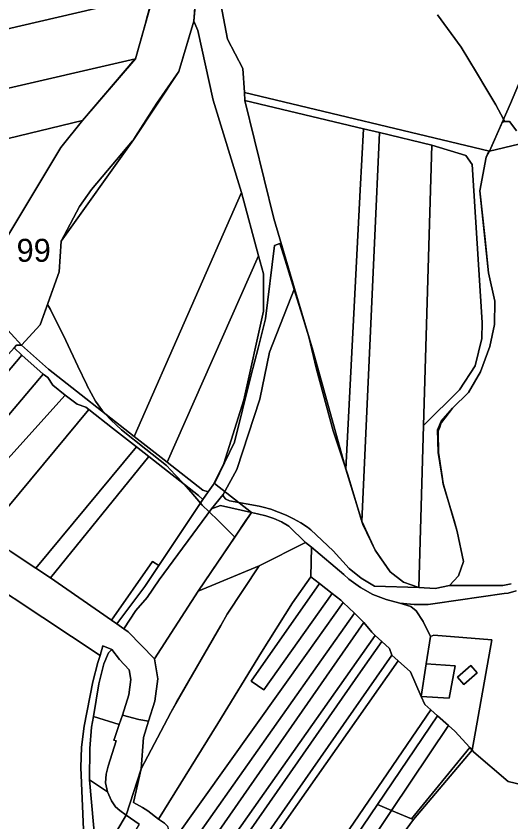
# Model space of a CAD drawing. Extents: x -521939 to -516426, y -1197857 to -1189551.
# Drawn here: x -519055 to -518732, y -1194197 to -1193670 of the extents above; entities that cross this region are included whole.
import ezdxf

# ---------------------------------------------------------------- set-up
doc = ezdxf.new("R2010")
doc.units = 0
for name, color, linetype in [('95560013', 7, 'Continuous'), ('95600013', 7, 'Continuous'), ('95610013', 7, 'Continuous'), ('95620013', 7, 'Continuous'), ('95630013', 7, 'Continuous'), ('95640013', 7, 'Continuous'), ('95660013', 7, 'Continuous')]:
    doc.layers.add(name, color=color, linetype=linetype)

msp = doc.modelspace()

# ---------------------------------------------------------------- linework, layer by layer
at = {"layer": '95560013'}
for points in [[(-518905.57, -1193725.38), (-518827.98, -1193743.9), (-518830.05, -1193784.07), (-518839.44, -1193966.29), (-518861.12, -1193888.71), (-518872.98, -1193848.37), (-518886.46, -1193802.5)], [(-518839.44, -1193966.29), (-518830.05, -1193784.07), (-518827.98, -1193743.9), (-518817.51, -1193746.43), (-518820.78, -1193818.72), (-518829, -1194000.44)], [(-518820.78, -1193818.72), (-518817.51, -1193746.43), (-518783.14, -1193754.66), (-518788.61, -1193937.78), (-518791.79, -1194043.69), (-518801.76, -1194040.34), (-518810.55, -1194033.52), (-518820.38, -1194019.37), (-518829, -1194000.44)], [(-518750.42, -1193870.62), (-518750.48, -1193880.94), (-518754.92, -1193898.93), (-518765.04, -1193914.64), (-518788.61, -1193937.78), (-518783.14, -1193754.66), (-518760.94, -1193761.33), (-518756.93, -1193767.29)]]:
    msp.add_lwpolyline(points, close=True, dxfattribs=at)
msp.add_lwpolyline([(-519113.44, -1194013.16), (-518999.95, -1194088.17), (-519001.62, -1194092.79), (-519004.84, -1194105.44), (-519010.43, -1194134.4), (-519012.2, -1194148.13), (-519012.79, -1194161.44), (-519009.11, -1194242.54)], dxfattribs=at)
at = {"layer": '95600013'}
msp.add_lwpolyline([(-518704.53, -1193662.76), (-518731.88, -1193727.36), (-518745.46, -1193758.59), (-518905.61, -1193720.26), (-518906.72, -1193704.58), (-518916.83, -1193685.28), (-518923.59, -1193649.53), (-518924.44, -1193591.77), (-518924.55, -1193580.35), (-518931.74, -1193565.63), (-518946.48, -1193538.74), (-518965.5, -1193501.95), (-518991.48, -1193439.69), (-519001.34, -1193412.48), (-519007.46, -1193393.47)], dxfattribs=at)
at = {"layer": '95610013'}
for points in [[(-519083.02, -1193619.12), (-518954.36, -1193589.13), (-518954.36, -1193611.78), (-518965.26, -1193656.42), (-519003.05, -1193665.21), (-519180.65, -1193706.52), (-519219.36, -1193651.4)], [(-518965.26, -1193656.42), (-518977.05, -1193698.16), (-519157.44, -1193739.69), (-519180.65, -1193706.52), (-519003.05, -1193665.21)], [(-519051.46, -1193885.31), (-519039.32, -1193871.96), (-519026.74, -1193837.39), (-519025.45, -1193817.42), (-518978.36, -1193751.04), (-518948.63, -1193706.4), (-518938.89, -1193673.47), (-518936.17, -1193679.58), (-518926.27, -1193725.26), (-518907.68, -1193785.6), (-518977.84, -1193945.14), (-519033.85, -1193901.07)], [(-519157.44, -1193739.69), (-518977.05, -1193698.16), (-519011.53, -1193738.42), (-519136.93, -1193768.86)], [(-519011.53, -1193738.42), (-519025.65, -1193756.19), (-519062.93, -1193818.34), (-519092.6, -1193832.11), (-519136.93, -1193768.86)], [(-518977.84, -1193945.14), (-518907.68, -1193785.6), (-518896.5, -1193826.92), (-518956.2, -1193961.92)], [(-518893.26, -1193863.08), (-518906.17, -1193921.14), (-518919.27, -1193962.65), (-518926.25, -1193976.62), (-518929.34, -1193981.24), (-518932.86, -1193980.21), (-518956.2, -1193961.92), (-518896.5, -1193826.92), (-518893.29, -1193838.77)], [(-519056.26, -1193887.06), (-519051.3, -1193891.79), (-519117.43, -1193970.23), (-519119.64, -1193964.92), (-519117.35, -1193952.56), (-519102.93, -1193930.08), (-519071.12, -1193903.44)], [(-519051.3, -1193891.79), (-519037.41, -1193904.25), (-519106.22, -1193985.64), (-519117.43, -1193970.23)], [(-519022.84, -1193918.09), (-519094.14, -1193996.93), (-519106.22, -1193985.64), (-519037.41, -1193904.25), (-519034.25, -1193906.47), (-519031.03, -1193911.53)], [(-519075.46, -1194009.08), (-519094.14, -1193996.93), (-519022.84, -1193918.09), (-519015.15, -1193923.98), (-519009.47, -1193925.89), (-519007.49, -1193927.44)], [(-519058.94, -1194019.99), (-519075.46, -1194009.08), (-519007.49, -1193927.44), (-518991.98, -1193939.56), (-518976.29, -1193951.9), (-519042.1, -1194031.06)], [(-519042.1, -1194031.06), (-518976.29, -1193951.9), (-518968.13, -1193958.14), (-519032.51, -1194037.38)], [(-519032.51, -1194037.38), (-518968.13, -1193958.14), (-518935.82, -1193983.64), (-518933.03, -1193986.3), (-518961.6, -1194029.39), (-518965.91, -1194026.75), (-518992.69, -1194065.12)], [(-518984.64, -1194070.77), (-518976.81, -1194058.82), (-518969.27, -1194050.28), (-518961.57, -1194038.67), (-518927.19, -1193992.35), (-518921.36, -1193990.1), (-518901.17, -1193994.65), (-518936.07, -1194046.25), (-518964.52, -1194090.45), (-518981.72, -1194072.81)], [(-518992.69, -1194065.12), (-518965.91, -1194026.75), (-518961.6, -1194029.39), (-518970.85, -1194043.01), (-518989.19, -1194067.6)], [(-518921.14, -1194068.53), (-518953.95, -1194125.44), (-518973.19, -1194162.2), (-518971.79, -1194141.85), (-518968.52, -1194131.03), (-518964.36, -1194117.94), (-518962.32, -1194103.53), (-518964.52, -1194090.45), (-518936.07, -1194046.25), (-518896.14, -1194029.57), (-518916.93, -1194061.2)], [(-518981.15, -1194097.64), (-518979.93, -1194103.79), (-518981.36, -1194113.88), (-518985.48, -1194127.27), (-518987.54, -1194133.31), (-519004.5, -1194128.01), (-519000.87, -1194106.75), (-518997.57, -1194093.58), (-518994.52, -1194086.35), (-518992.34, -1194084.24), (-518987.46, -1194090.71)], [(-518987.54, -1194133.31), (-518990.75, -1194142.5), (-518991.04, -1194143.46), (-518989.57, -1194143.91), (-518994.89, -1194160.62), (-518996.22, -1194165.66), (-518996.46, -1194171.39), (-518995.35, -1194177.39), (-519007.1, -1194169.38), (-519006.82, -1194148.88), (-519005.71, -1194135.09), (-519004.5, -1194128.01)], [(-518983, -1194192.63), (-518995.91, -1194214.24), (-519001.58, -1194230.24), (-519007.1, -1194169.38), (-518995.35, -1194177.39), (-518992.7, -1194183.09), (-518989.97, -1194187.05), (-518987.24, -1194189.51)]]:
    msp.add_lwpolyline(points, close=True, dxfattribs=at)
at = {"layer": '95620013'}
msp.add_lwpolyline([(-519065.01, -1193870.53), (-519062.93, -1193818.34), (-519025.65, -1193756.19), (-519011.53, -1193738.42), (-518977.05, -1193698.16), (-518965.26, -1193656.42), (-518954.36, -1193611.78), (-518954.36, -1193589.13), (-518956.05, -1193564.77), (-518969.16, -1193519.14), (-518945.93, -1193558.15), (-518934.47, -1193585.52), (-518933.01, -1193608.51), (-518935.29, -1193627.86), (-518936.87, -1193650.95), (-518938.89, -1193673.47), (-518948.63, -1193706.4), (-518978.36, -1193751.04), (-519025.45, -1193817.42), (-519026.74, -1193837.39), (-519039.32, -1193871.96), (-519051.46, -1193885.31)], close=True, dxfattribs=at)
at = {"layer": '95630013'}
for points in [[(-519058.94, -1194019.99), (-519042.1, -1194031.06), (-519032.51, -1194037.38), (-518992.69, -1194065.12), (-518989.19, -1194067.6), (-518984.64, -1194070.77), (-518981.72, -1194072.81), (-518964.52, -1194090.45), (-518962.32, -1194103.53), (-518964.36, -1194117.94), (-518968.52, -1194131.03), (-518974.87, -1194130.07), (-518985.48, -1194127.27), (-518981.36, -1194113.88), (-518979.93, -1194103.79), (-518981.15, -1194097.64), (-518987.46, -1194090.71), (-518992.34, -1194084.24), (-518998.31, -1194081.79), (-518999.95, -1194088.17), (-519113.44, -1194013.16)], [(-518974.63, -1194198.5), (-518983, -1194192.63), (-518987.24, -1194189.51), (-518989.97, -1194187.05), (-518992.7, -1194183.09), (-518995.35, -1194177.39), (-518996.46, -1194171.39), (-518996.22, -1194165.66), (-518994.89, -1194160.62), (-518989.57, -1194143.91), (-518991.04, -1194143.46), (-518990.75, -1194142.5), (-518987.54, -1194133.31), (-518985.48, -1194127.27), (-518974.87, -1194130.07), (-518968.52, -1194131.03), (-518971.79, -1194141.85), (-518973.19, -1194162.2), (-518978.25, -1194184.19), (-518972.32, -1194187.45), (-518968.98, -1194189.71), (-518961.94, -1194195.09), (-518958.03, -1194197.83)], [(-518855.61, -1194277.58), (-518795.25, -1194195.41), (-518756.87, -1194150.17), (-518755.73, -1194151.42), (-518733.26, -1194170.62), (-518723.34, -1194172.97)]]:
    msp.add_lwpolyline(points, dxfattribs=at)
for points in [[(-518901.31, -1194104.95), (-518893.16, -1194110.69), (-518848.33, -1194047.58), (-518842.7, -1194051.99), (-518841.13, -1194053.49), (-518864.72, -1194086.62), (-518968.6, -1194232.51), (-518977.21, -1194230.09), (-518959.36, -1194206.84), (-518956.21, -1194205.24), (-518955.26, -1194202.46), (-518955.86, -1194199.89), (-518958.03, -1194197.83), (-518961.94, -1194195.09), (-518923.17, -1194132.68), (-518894.5, -1194086.07), (-518874.4, -1194053.74), (-518862.24, -1194036.73), (-518856.71, -1194041.04)], [(-518893.16, -1194110.69), (-518901.31, -1194104.95), (-518856.71, -1194041.04), (-518848.33, -1194047.58)], [(-518841.13, -1194053.49), (-518833.88, -1194060.52), (-518855.36, -1194090.97), (-518957.42, -1194235.65), (-518962.5, -1194234.23), (-518968.6, -1194232.51), (-518864.72, -1194086.62)], [(-518957.42, -1194235.65), (-518855.36, -1194090.97), (-518833.88, -1194060.52), (-518829.19, -1194065.02), (-518827.78, -1194066.65), (-518939.75, -1194227.68), (-518947.28, -1194238.51)], [(-518827.78, -1194066.65), (-518822.48, -1194072.97), (-518820.23, -1194075.04), (-518933.71, -1194236.34), (-518939.75, -1194227.68)], [(-518937.68, -1194242.28), (-518933.71, -1194236.34), (-518820.23, -1194075.04), (-518815.94, -1194078.99), (-518828.25, -1194096.65), (-518931.93, -1194245.39)], [(-518815.94, -1194078.99), (-518810.87, -1194083.64), (-518809.4, -1194088.06), (-518922.65, -1194250.42), (-518931.93, -1194245.39), (-518828.25, -1194096.65)], [(-518809.4, -1194088.06), (-518805.32, -1194091.65), (-518918.24, -1194252.79), (-518922.65, -1194250.42)], [(-518884.06, -1194270.49), (-518901.77, -1194262.69), (-518903.43, -1194258.95), (-518912.68, -1194255.11), (-518916.45, -1194253.54), (-518918.24, -1194252.79), (-518805.32, -1194091.65), (-518797.22, -1194098.85), (-518790.2, -1194114.91), (-518787.71, -1194120.29), (-518783.83, -1194123.78)], [(-518884.06, -1194270.49), (-518783.83, -1194123.78), (-518779.55, -1194127.56), (-518818.81, -1194185.64), (-518877.97, -1194273.16), (-518883.22, -1194270.86)], [(-518818.81, -1194185.64), (-518779.55, -1194127.56), (-518772.3, -1194134.01), (-518809.58, -1194189.47)], [(-518809.58, -1194189.47), (-518772.3, -1194134.01), (-518768.19, -1194137.67), (-518758.5, -1194148.35), (-518796.43, -1194194.92)], [(-518756.87, -1194150.17), (-518795.25, -1194195.41), (-518796.43, -1194194.92), (-518758.5, -1194148.35)], [(-518877.97, -1194273.16), (-518818.81, -1194185.64), (-518809.58, -1194189.47), (-518867.56, -1194276.25), (-518869.07, -1194275.8), (-518871.17, -1194275.18)], [(-518796.43, -1194194.92), (-518795.25, -1194195.41), (-518855.61, -1194277.58), (-518862.81, -1194277.65), (-518867.56, -1194276.25), (-518809.58, -1194189.47)]]:
    msp.add_lwpolyline(points, close=True, dxfattribs=at)
at = {"layer": '95640013'}
for points in [[(-518923.59, -1193649.53), (-518916.83, -1193685.28), (-518906.72, -1193704.58), (-518905.61, -1193720.26), (-518905.57, -1193725.38), (-518886.46, -1193802.5), (-518872.98, -1193848.37), (-518889.3, -1193889.95), (-518895.73, -1193920.57), (-518910.79, -1193966.72), (-518919.72, -1193983.02), (-518927.19, -1193992.35), (-518961.57, -1194038.67), (-518969.27, -1194050.28), (-518976.81, -1194058.82), (-518984.64, -1194070.77), (-518989.19, -1194067.6), (-518970.85, -1194043.01), (-518961.6, -1194029.39), (-518933.03, -1193986.3), (-518929.34, -1193981.24), (-518926.25, -1193976.62), (-518919.27, -1193962.65), (-518906.17, -1193921.14), (-518893.26, -1193863.08), (-518893.29, -1193838.77), (-518896.5, -1193826.92), (-518907.68, -1193785.6), (-518926.27, -1193725.26), (-518936.17, -1193679.58), (-518938.89, -1193673.47), (-518936.87, -1193650.95)], [(-518726.44, -1193753.95), (-518745.46, -1193758.59), (-518731.88, -1193727.36), (-518704.53, -1193662.76)], [(-518731.43, -1194041.27), (-518736.71, -1194042.42), (-518771.79, -1194042.37), (-518765.79, -1194036.21), (-518762.62, -1194026.86), (-518766.59, -1194007.09), (-518775.73, -1193975.78), (-518779.1, -1193955.43), (-518779.51, -1193940.67), (-518777.04, -1193935.11), (-518769.73, -1193926.62), (-518759.35, -1193916.24), (-518751.49, -1193902.69), (-518745.35, -1193886.28), (-518742.33, -1193871.76), (-518742.12, -1193856.49), (-518746.09, -1193838.05), (-518751.93, -1193784.48), (-518747.81, -1193762.41), (-518745.46, -1193758.59), (-518726.44, -1193753.95)], [(-519065.01, -1193870.53), (-519051.46, -1193885.31), (-519033.85, -1193901.07), (-518977.84, -1193945.14), (-518956.2, -1193961.92), (-518932.86, -1193980.21), (-518929.34, -1193981.24), (-518933.03, -1193986.3), (-518935.82, -1193983.64), (-518968.13, -1193958.14), (-518976.29, -1193951.9), (-518991.98, -1193939.56), (-519007.49, -1193927.44), (-519009.47, -1193925.89), (-519015.15, -1193923.98), (-519022.84, -1193918.09), (-519031.03, -1193911.53), (-519034.25, -1193906.47), (-519037.41, -1193904.25), (-519051.3, -1193891.79), (-519056.26, -1193887.06)], [(-518728.17, -1194045.98), (-518733.31, -1194047.39), (-518735.95, -1194047.77), (-518780.98, -1194054.19), (-518785.58, -1194054.84), (-518794.87, -1194054.96), (-518804.1, -1194053.89), (-518813.11, -1194051.65), (-518821.77, -1194048.27), (-518829.92, -1194043.82), (-518837.43, -1194038.35), (-518840.81, -1194035.16), (-518861.8, -1194017.37), (-518865.76, -1194014.41), (-518876.72, -1194003.63), (-518881.5, -1194000.92), (-518886.53, -1193998.68), (-518891.75, -1193996.93), (-518897.11, -1193995.69), (-518901.17, -1193994.65), (-518921.36, -1193990.1), (-518927.19, -1193992.35), (-518919.72, -1193983.02), (-518919.42, -1193984.21), (-518917.8, -1193986.11), (-518915.51, -1193987.1), (-518896.17, -1193990.58), (-518893.56, -1193991.17), (-518888.41, -1193992.64), (-518883.37, -1193994.4), (-518878.43, -1193996.47), (-518873.62, -1193998.81), (-518868.96, -1194001.44), (-518864.46, -1194004.33), (-518862.25, -1194005.95), (-518847.72, -1194019.68), (-518837.23, -1194031.38), (-518829.44, -1194037.71), (-518820.8, -1194042.81), (-518791.79, -1194043.69), (-518780.95, -1194044.34), (-518771.79, -1194042.37), (-518736.71, -1194042.42), (-518731.43, -1194041.27)], [(-518723.34, -1194172.97), (-518733.26, -1194170.62), (-518755.73, -1194151.42), (-518756.87, -1194150.17), (-518743.97, -1194077.98), (-518781.91, -1194074.8), (-518784.2, -1194075.75), (-518788.94, -1194065.87), (-518793.56, -1194058.95), (-518797.05, -1194056.07), (-518804.1, -1194053.89), (-518794.87, -1194054.96), (-518785.58, -1194054.84), (-518780.98, -1194054.19), (-518735.95, -1194047.77), (-518733.31, -1194047.39), (-518728.17, -1194045.98)], [(-519009.11, -1194242.54), (-519012.79, -1194161.44), (-519012.2, -1194148.13), (-519010.43, -1194134.4), (-519004.84, -1194105.44), (-519001.62, -1194092.79), (-518999.95, -1194088.17), (-518998.31, -1194081.79), (-518992.34, -1194084.24), (-518994.52, -1194086.35), (-518997.57, -1194093.58), (-519000.87, -1194106.75), (-519004.5, -1194128.01), (-519005.71, -1194135.09), (-519006.82, -1194148.88), (-519007.1, -1194169.38), (-519001.58, -1194230.24)]]:
    msp.add_lwpolyline(points, dxfattribs=at)
for points in [[(-518750.48, -1193880.94), (-518750.42, -1193870.62), (-518756.93, -1193767.29), (-518760.94, -1193761.33), (-518783.14, -1193754.66), (-518817.51, -1193746.43), (-518827.98, -1193743.9), (-518905.57, -1193725.38), (-518905.61, -1193720.26), (-518745.46, -1193758.59), (-518747.81, -1193762.41), (-518751.93, -1193784.48), (-518746.09, -1193838.05), (-518742.12, -1193856.49), (-518742.33, -1193871.76), (-518745.35, -1193886.28), (-518751.49, -1193902.69), (-518759.35, -1193916.24), (-518769.73, -1193926.62), (-518777.04, -1193935.11), (-518779.51, -1193940.67), (-518779.1, -1193955.43), (-518775.73, -1193975.78), (-518766.59, -1194007.09), (-518762.62, -1194026.86), (-518765.79, -1194036.21), (-518771.79, -1194042.37), (-518780.95, -1194044.34), (-518791.79, -1194043.69), (-518788.61, -1193937.78), (-518765.04, -1193914.64), (-518754.92, -1193898.93)], [(-518872.98, -1193848.37), (-518861.12, -1193888.71), (-518839.44, -1193966.29), (-518829, -1194000.44), (-518820.38, -1194019.37), (-518810.55, -1194033.52), (-518801.76, -1194040.34), (-518791.79, -1194043.69), (-518820.8, -1194042.81), (-518829.44, -1194037.71), (-518837.23, -1194031.38), (-518847.72, -1194019.68), (-518862.25, -1194005.95), (-518864.46, -1194004.33), (-518868.96, -1194001.44), (-518873.62, -1193998.81), (-518878.43, -1193996.47), (-518883.37, -1193994.4), (-518888.41, -1193992.64), (-518893.56, -1193991.17), (-518896.17, -1193990.58), (-518915.51, -1193987.1), (-518917.8, -1193986.11), (-518919.42, -1193984.21), (-518919.72, -1193983.02), (-518910.79, -1193966.72), (-518895.73, -1193920.57), (-518889.3, -1193889.95)], [(-518901.17, -1193994.65), (-518897.11, -1193995.69), (-518891.75, -1193996.93), (-518886.53, -1193998.68), (-518881.5, -1194000.92), (-518876.72, -1194003.63), (-518865.76, -1194014.41), (-518896.14, -1194029.57), (-518936.07, -1194046.25)], [(-518894.5, -1194086.07), (-518923.17, -1194132.68), (-518961.94, -1194195.09), (-518968.98, -1194189.71), (-518972.32, -1194187.45), (-518978.25, -1194184.19), (-518973.19, -1194162.2), (-518953.95, -1194125.44), (-518921.14, -1194068.53), (-518916.93, -1194061.2), (-518896.14, -1194029.57), (-518865.76, -1194014.41), (-518861.8, -1194017.37), (-518862.24, -1194036.73), (-518874.4, -1194053.74)], [(-518862.24, -1194036.73), (-518861.8, -1194017.37), (-518840.81, -1194035.16), (-518837.43, -1194038.35), (-518829.92, -1194043.82), (-518821.77, -1194048.27), (-518813.11, -1194051.65), (-518804.1, -1194053.89), (-518797.05, -1194056.07), (-518793.56, -1194058.95), (-518788.94, -1194065.87), (-518784.2, -1194075.75), (-518786.96, -1194093.75), (-518790.2, -1194114.91), (-518797.22, -1194098.85), (-518805.32, -1194091.65), (-518809.4, -1194088.06), (-518810.87, -1194083.64), (-518815.94, -1194078.99), (-518820.23, -1194075.04), (-518822.48, -1194072.97), (-518827.78, -1194066.65), (-518829.19, -1194065.02), (-518833.88, -1194060.52), (-518841.13, -1194053.49), (-518842.7, -1194051.99), (-518848.33, -1194047.58), (-518856.71, -1194041.04)], [(-518783.83, -1194123.78), (-518787.71, -1194120.29), (-518790.2, -1194114.91), (-518771.82, -1194116.17), (-518767.96, -1194095.04), (-518786.96, -1194093.75), (-518784.2, -1194075.75), (-518781.91, -1194074.8), (-518743.97, -1194077.98), (-518756.87, -1194150.17), (-518758.5, -1194148.35), (-518768.19, -1194137.67), (-518772.3, -1194134.01), (-518779.55, -1194127.56)], [(-518786.96, -1194093.75), (-518767.96, -1194095.04), (-518771.82, -1194116.17), (-518790.2, -1194114.91)], [(-518753.59, -1194099.63), (-518757.64, -1194094.78), (-518766.41, -1194102.26), (-518762.33, -1194107.13)], [(-518766.41, -1194102.26), (-518757.64, -1194094.78), (-518753.59, -1194099.63), (-518762.33, -1194107.13)], [(-518983, -1194192.63), (-518974.63, -1194198.5), (-518987.65, -1194220.1), (-518988.08, -1194220.82), (-518995.91, -1194214.24)]]:
    msp.add_lwpolyline(points, close=True, dxfattribs=at)
at = {"layer": '95660013'}
for points in [[(-519062.93, -1193818.34), (-519025.65, -1193756.19), (-519011.53, -1193738.42), (-518977.29, -1193698.44), (-518977.05, -1193698.17), (-518970.3, -1193674.26), (-518969.71, -1193672.16), (-518966.86, -1193662.08)], [(-518966.86, -1193662.08), (-518969.71, -1193672.16), (-518970.3, -1193674.26), (-518977.05, -1193698.17), (-518977.29, -1193698.44), (-519011.53, -1193738.42), (-519025.65, -1193756.19), (-519062.93, -1193818.34)], [(-518937.86, -1193661.96), (-518938.89, -1193673.47), (-518940.87, -1193680.16), (-518948.63, -1193706.4), (-518963.01, -1193727.14), (-518976.93, -1193748.89), (-518978.36, -1193751.04), (-518978.82, -1193751.69), (-519005.74, -1193783.68), (-519013.49, -1193794.7), (-519025.45, -1193817.42), (-519026.74, -1193837.39), (-519034.5, -1193858.71), (-519039.32, -1193871.96), (-519051.47, -1193885.32), (-519054.65, -1193885.29), (-519056.26, -1193887.06)], [(-518779.5, -1193669.41), (-518764.03, -1193690.5), (-518754.06, -1193707.14), (-518747.34, -1193718.38), (-518741.49, -1193728.17), (-518736.38, -1193737.69), (-518735.54, -1193739.25), (-518736.2, -1193739.28), (-518737.09, -1193739.33), (-518745.46, -1193758.59), (-518746.02, -1193758.46), (-518747.81, -1193762.41), (-518751.92, -1193784.41), (-518751.93, -1193784.48), (-518751.92, -1193784.57), (-518748.67, -1193814.38), (-518746.09, -1193838.05), (-518742.12, -1193856.49), (-518742.33, -1193871.76), (-518745.35, -1193886.28), (-518751.49, -1193902.69), (-518759.35, -1193916.24), (-518769.73, -1193926.62), (-518776.92, -1193935.92), (-518777.25, -1193936.76), (-518778.08, -1193938.85), (-518778.76, -1193940.54), (-518779.19, -1193941.63), (-518779.18, -1193942.08), (-518778.83, -1193955.42), (-518776.49, -1193971.18), (-518775.75, -1193976.18), (-518768.69, -1194000), (-518766.59, -1194007.09), (-518762.62, -1194026.86), (-518765.79, -1194036.21), (-518771.79, -1194042.37), (-518780.95, -1194044.34), (-518791.78, -1194043.69), (-518801.76, -1194040.34), (-518810.55, -1194033.52), (-518813.39, -1194029.43), (-518817.1, -1194024.09), (-518820.38, -1194019.37), (-518828.34, -1194002.61), (-518828.92, -1194000.61), (-518829, -1194000.44), (-518829.13, -1194000), (-518838.25, -1193970.19), (-518847.75, -1193941.24), (-518858.55, -1193901.08), (-518863.74, -1193879.95), (-518866.33, -1193871.41), (-518867.01, -1193869.16), (-518873.23, -1193849.01), (-518880.07, -1193826.88), (-518881.74, -1193821.56), (-518882.54, -1193818.99), (-518885.98, -1193820.28), (-518891.87, -1193868.1), (-518896.82, -1193887.32), (-518901.55, -1193905.66), (-518912.19, -1193948.64), (-518925.22, -1193975.67), (-518901.17, -1193994.65), (-518904.79, -1194000), (-518912.08, -1194010.78), (-518920.39, -1194002.57), (-518922.99, -1194000), (-518928.69, -1193994.37), (-518933.35, -1193990.03), (-518934.54, -1193988.58), (-518940.45, -1193981.35), (-518945.43, -1193976.06), (-518951.04, -1193970.09), (-518956.73, -1193964.05), (-518970.12, -1193953.39), (-518986, -1193940.64), (-518993.07, -1193934.15), (-518996.65, -1193930.34), (-518998.52, -1193928.35), (-519003.04, -1193921.86), (-519008.72, -1193911.43), (-519008.8, -1193911.25), (-519014.56, -1193899), (-519022.4, -1193882.34), (-519032.6, -1193862.05), (-519034.5, -1193858.71), (-519026.74, -1193837.39), (-519025.45, -1193817.42), (-519013.49, -1193794.7), (-519005.74, -1193783.68), (-518978.82, -1193751.69), (-518978.36, -1193751.04), (-518976.93, -1193748.89), (-518963.01, -1193727.14), (-518948.63, -1193706.4), (-518940.87, -1193680.16), (-518938.89, -1193673.47), (-518937.86, -1193661.96)], [(-518727.95, -1193745.32), (-518731.62, -1193740.26), (-518732.49, -1193739.07), (-518734.63, -1193739.19), (-518735.08, -1193739.22), (-518735.54, -1193739.25), (-518736.38, -1193737.69), (-518741.49, -1193728.17), (-518747.34, -1193718.38), (-518754.06, -1193707.14), (-518764.03, -1193690.5), (-518779.5, -1193669.41)], [(-518995.91, -1194214.24), (-518983, -1194192.63), (-518973.19, -1194162.2), (-518953.95, -1194125.44), (-518950.06, -1194118.7), (-518921.14, -1194068.53), (-518916.93, -1194061.2), (-518896.14, -1194029.57), (-518936.07, -1194046.25), (-518912.08, -1194010.78), (-518904.79, -1194000), (-518901.17, -1193994.65), (-518925.22, -1193975.67), (-518912.19, -1193948.64), (-518901.55, -1193905.66), (-518896.82, -1193887.32), (-518891.87, -1193868.1), (-518885.98, -1193820.28), (-518882.54, -1193818.99), (-518881.74, -1193821.56), (-518880.07, -1193826.88), (-518873.23, -1193849.01), (-518867.01, -1193869.16), (-518866.33, -1193871.41), (-518863.74, -1193879.95), (-518858.55, -1193901.08), (-518847.75, -1193941.24), (-518838.25, -1193970.19), (-518829.13, -1194000), (-518829, -1194000.44), (-518828.92, -1194000.61), (-518828.34, -1194002.61), (-518820.38, -1194019.37), (-518817.1, -1194024.09), (-518813.39, -1194029.43), (-518810.55, -1194033.52), (-518801.76, -1194040.34), (-518791.78, -1194043.69), (-518780.95, -1194044.34), (-518771.79, -1194042.37), (-518765.79, -1194036.21), (-518762.62, -1194026.86), (-518766.59, -1194007.09), (-518768.69, -1194000), (-518775.75, -1193976.18), (-518776.49, -1193971.18), (-518778.83, -1193955.42), (-518779.18, -1193942.08), (-518779.19, -1193941.63), (-518778.76, -1193940.54), (-518778.08, -1193938.85), (-518777.25, -1193936.76), (-518776.92, -1193935.92), (-518769.73, -1193926.62), (-518759.35, -1193916.24), (-518751.49, -1193902.69), (-518745.35, -1193886.28), (-518742.33, -1193871.76), (-518742.12, -1193856.49), (-518746.09, -1193838.05), (-518748.67, -1193814.38), (-518751.92, -1193784.57), (-518751.93, -1193784.48), (-518751.92, -1193784.41), (-518747.81, -1193762.41), (-518746.02, -1193758.46), (-518745.46, -1193758.59), (-518737.09, -1193739.33), (-518736.2, -1193739.28), (-518735.54, -1193739.25), (-518735.08, -1193739.22), (-518734.63, -1193739.19), (-518732.49, -1193739.07), (-518731.62, -1193740.26), (-518727.95, -1193745.32)], [(-519056.26, -1193887.06), (-519054.65, -1193885.29), (-519051.47, -1193885.32), (-519039.32, -1193871.96), (-519034.5, -1193858.71), (-519032.6, -1193862.05), (-519022.4, -1193882.34), (-519014.56, -1193899), (-519008.8, -1193911.25), (-519008.72, -1193911.43), (-519003.04, -1193921.86), (-518998.52, -1193928.35), (-518996.65, -1193930.34), (-518993.07, -1193934.15), (-518986, -1193940.64), (-518970.12, -1193953.39), (-518956.73, -1193964.05), (-518951.04, -1193970.09), (-518945.43, -1193976.06), (-518940.45, -1193981.35), (-518934.54, -1193988.58), (-518933.35, -1193990.03), (-518928.69, -1193994.37), (-518922.99, -1194000), (-518920.39, -1194002.57), (-518912.08, -1194010.78), (-518936.07, -1194046.25), (-518896.14, -1194029.57), (-518916.93, -1194061.2), (-518921.14, -1194068.53), (-518950.06, -1194118.7), (-518953.95, -1194125.44), (-518973.19, -1194162.2), (-518983, -1194192.63), (-518995.91, -1194214.24)]]:
    msp.add_lwpolyline(points, dxfattribs=at)

# ---------------------------------------------------------------- texts
msp.add_text('99', height=15, rotation=0, dxfattribs=at).set_placement((-519054.66, -1193830.83))

doc.saveas('drawing.dxf')
